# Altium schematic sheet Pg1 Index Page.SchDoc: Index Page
size 431 x 279 mm; Date: Not shown in title block; ApprovedBy: Not shown in title block; CheckedBy: Not shown in title block; Author: Not shown in title block; CompanyName: Not shown in title block; Engineer: Not shown in title block; Organization: Not shown in title block; Address1: Not shown in title block; Address2: Not shown in title block; Address3: Not shown in title block; Address4: Not shown in title block; DocumentNumber: 1; Revision: Use project parameter SCH_Rev; SheetNumber: 1; SheetTotal: 8; PageSetup: Record=PageOptions|CenterHorizontal=True|CenterVertical=True|PrintScale=1.00|XCorrection=1.00|YCorrection=1.00|PrintKind=0|BorderSize=5000000|LeftOffset=0|BottomOffset=0|Orientation=2|PaperLength=1000|PaperWidth=1000|Scale=100|PaperSource=15|PrintQuality=600|MediaType=1|DitherType=10|PaperKind=Letter|PrintScaleMode=1
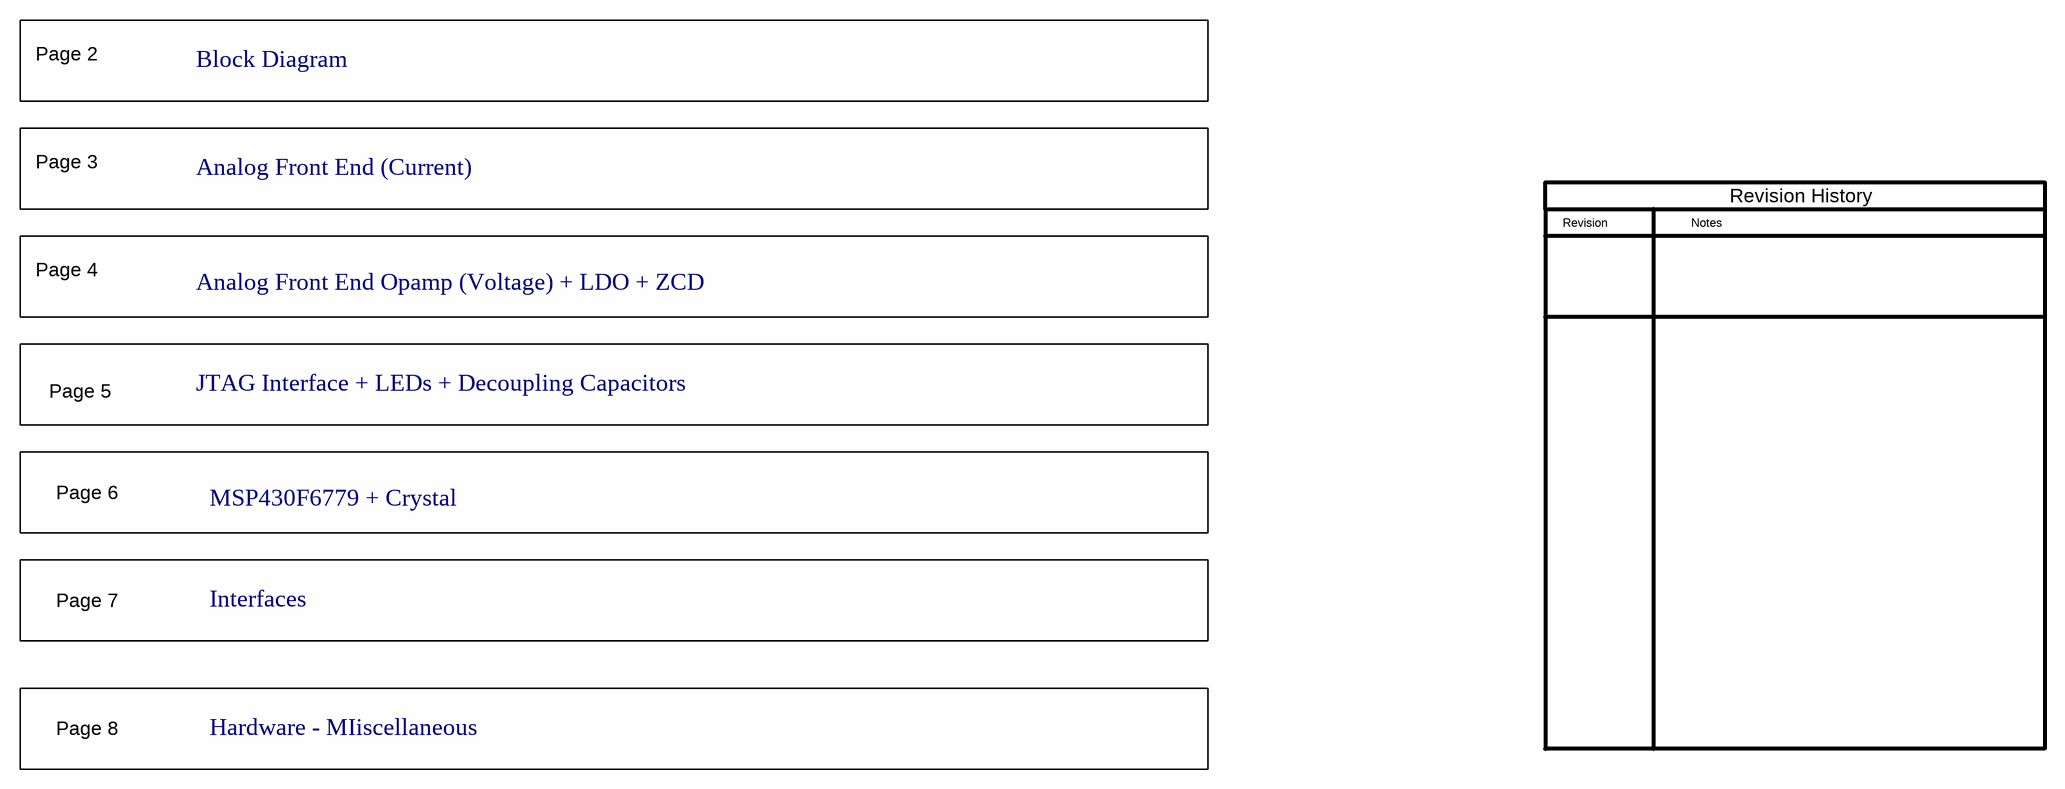
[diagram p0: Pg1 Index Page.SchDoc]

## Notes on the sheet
- Page 2
- Block Diagram
- Page 3
- Analog Front End (Current)
- Revision
- Notes
- Revision History
- Page 4
- Analog Front End Opamp (Voltage) + LDO + ZCD
- Page 5
- JTAG Interface + LEDs + Decoupling Capacitors
- Page 6
- MSP430F6779 + Crystal
- Page 7
- Interfaces
- Page 8
- Hardware - MIiscellaneous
